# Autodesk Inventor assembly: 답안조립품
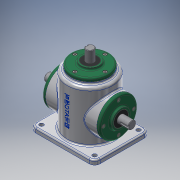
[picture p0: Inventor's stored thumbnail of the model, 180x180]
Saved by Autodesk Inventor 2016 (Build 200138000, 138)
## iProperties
Created: 2021-02
Part Number: 답안조립품
Material: 일반
Document SubType Name: Assembly
Designer: user
Author: user
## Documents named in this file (16)
- C:\Users\user\Desktop\710206V1005\답안조립품.iam
- C:\Users\user\Desktop\710206V1005\본체.ipt
- C:\Users\user\Desktop\710206V1005\메인 베벨기어.ipt
- C:\Users\user\Desktop\710206V1005\메인 축.ipt
- 메인 축.ipt
- C:\Users\user\Desktop\710206V1005\베어링 6203.ipt
- C:\Users\user\Desktop\710206V1005\볼트 M4.ipt
- 볼트 M4.ipt
- C:\Users\user\Desktop\710206V1005\서브 베벨기어.ipt
- C:\Users\user\Desktop\710206V1005\서브 축.ipt
- 서브 축.ipt
- C:\Users\user\Desktop\710206V1005\오일 실.ipt
- 오일 실.ipt
- C:\Users\user\Desktop\710206V1005\커버.ipt
- C:\Users\user\Desktop\710206V1005\키 4x4.ipt
- C:\Users\user\Desktop\710206V1005\키 5x5.ipt
